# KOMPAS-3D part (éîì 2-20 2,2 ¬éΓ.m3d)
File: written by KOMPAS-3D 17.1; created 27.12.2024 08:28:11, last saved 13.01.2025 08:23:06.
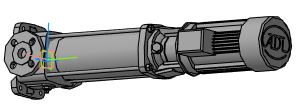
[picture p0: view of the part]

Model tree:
1. Операция без истории:4  (labels: ВМН 2-20 2,2 кВт)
